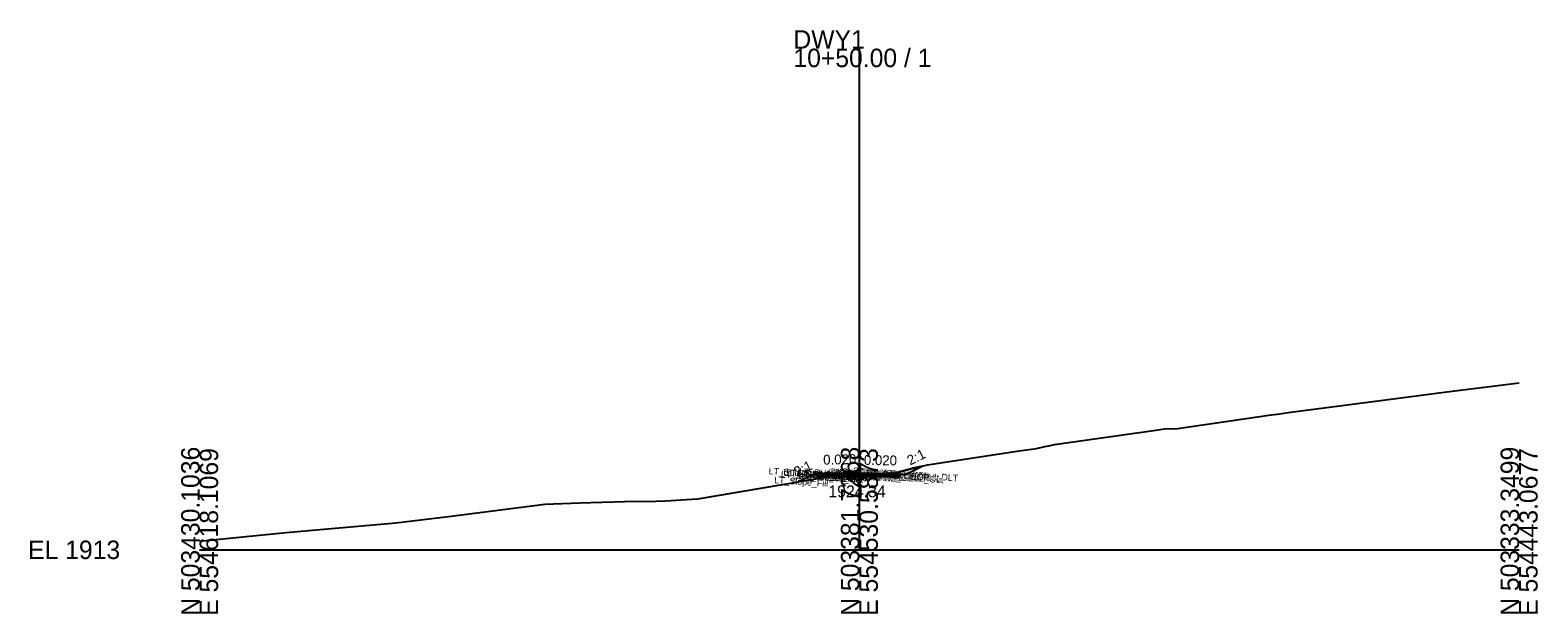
# Model space of a CAD drawing. Extents: x -26 to 203, y -10 to 1558.
# Drawn here: x -25.7 to 202.8, y 490.3 to 578.7 of the extents above; entities that cross this region are included whole.
import ezdxf

# ---------------------------------------------------------------- set-up
doc = ezdxf.new("R2010")
doc.units = 0
for name, color, linetype in [('Default', 7, 'Continuous'), ('Exist Cross Section Cell', 7, 'Continuous'), ('Exist XS Center Line Elevation Label', 7, 'Continuous'), ('Exist XS Ground Line', 7, 'Continuous'), ('Prop CMT Pvmt Course 1', 7, 'Continuous'), ('Prop CMT Pvmt Course 2', 7, 'Continuous'), ('Prop CMT Pvmt Surface', 7, 'Continuous'), ('Prop CMT Shld Paved Course 1', 7, 'Continuous'), ('Prop CMT Shld Paved Course 2', 7, 'Continuous'), ('Prop CMT Slope Grass', 7, 'Continuous'), ('Prop CMT Subgrade Earthwork', 7, 'Continuous'), ('Prop XS Earthwork Shape', 7, 'Continuous'), ('Prop XS SE Text', 7, 'Continuous'), ('Prop XS Side Slope Text', 7, 'Continuous'), ('Typical Text Asphalt at Bridge Approach CELL', 7, 'Continuous')]:
    doc.layers.add(name, color=color, linetype=linetype)

msp = doc.modelspace()

# ---------------------------------------------------------------- linework, layer by layer
at = {"layer": 'Exist Cross Section Cell'}
for p, q in [((100, 500), (100, 575.89)), ((0, 500), (100, 500)), ((100, 500), (200, 500))]:
    msp.add_line(p, q, dxfattribs=at)
at = {"layer": 'Exist XS Ground Line'}
for p, q in [((179, 522.6), (189.03, 523.93)), ((189.03, 523.93), (200, 525.3)), ((165.01, 520.8), (179, 522.6)), ((147.93, 518.32), (162.04, 520.41)), ((162.04, 520.41), (163.71, 520.6)), ((163.71, 520.6), (165.01, 520.8)), ((129.56, 515.96), (144.92, 518.1)), ((144.92, 518.1), (146.24, 518.34)), ((146.24, 518.34), (147.18, 518.35)), ((147.18, 518.35), (147.93, 518.32)), ((115.27, 513.63), (124.24, 515.01)), ((124.24, 515.01), (126.85, 515.36)), ((126.85, 515.36), (128.09, 515.66)), ((128.09, 515.66), (128.99, 515.8)), ((128.99, 515.8), (129.56, 515.96)), ((105.35, 511.63), (108.36, 512.4)), ((108.36, 512.4), (109.32, 512.63)), ((109.32, 512.63), (110.31, 512.87)), ((110.31, 512.87), (115.27, 513.63)), ((75.52, 507.74), (94.91, 511.02)), ((94.91, 511.02), (95.83, 511.17)), ((95.83, 511.17), (100, 511.34)), ((100, 511.34), (105, 511.54)), ((105, 511.54), (105.35, 511.63)), ((64.38, 507.31), (69.13, 507.38)), ((69.13, 507.38), (70.66, 507.4)), ((70.66, 507.4), (72.25, 507.52)), ((72.25, 507.52), (74.58, 507.66)), ((74.58, 507.66), (75.52, 507.74)), ((37.74, 505.03), (52.31, 506.92)), ((52.31, 506.92), (57.63, 507.12)), ((57.63, 507.12), (64.38, 507.31)), ((13.13, 502.6), (29.72, 504.11)), ((29.72, 504.11), (37.74, 505.03)), ((0, 501.33), (13.13, 502.6))]:
    msp.add_line(p, q, dxfattribs=at)
at = {"layer": 'Prop CMT Pvmt Course 1'}
for points in [[(100, 511.67), (95, 511.57)], [(95, 511.57), (95, 511.32)], [(95, 511.32), (100, 511.42)], [(100, 511.42), (100, 511.67)], [(100, 511.67), (105, 511.57)], [(100, 511.42), (100, 511.67)], [(105, 511.32), (100, 511.42)], [(105, 511.57), (105, 511.32)]]:
    msp.add_lwpolyline(points, dxfattribs=at)
msp.add_lwpolyline([(100, 511.42), (100, 511.54), (100, 511.54), (100, 511.42)], close=True, dxfattribs=at)
msp.add_lwpolyline([(100, 511.42), (100, 511.54), (100, 511.54), (100, 511.42)], close=True, dxfattribs=at)
at = {"layer": 'Prop CMT Pvmt Course 2'}
for points in [[(100, 511.42), (95, 511.32)], [(95, 511.32), (95, 511.07)], [(95, 511.07), (100, 511.17)], [(100, 511.17), (100, 511.42)], [(100, 511.17), (100, 511.42)], [(100, 511.42), (105, 511.32)], [(105, 511.07), (100, 511.17)], [(105, 511.32), (105, 511.07)]]:
    msp.add_lwpolyline(points, dxfattribs=at)
at = {"layer": 'Prop CMT Pvmt Surface'}
for points in [[(100, 511.67), (95, 511.57)], [(100, 511.67), (105, 511.57)]]:
    msp.add_lwpolyline(points, dxfattribs=at)
at = {"layer": 'Prop CMT Shld Paved Course 1'}
for points in [[(95, 511.57), (94.74, 511.31)], [(94.74, 511.31), (95, 511.32)], [(95, 511.32), (95, 511.57)], [(105, 511.57), (105.26, 511.31)], [(105, 511.32), (105, 511.57)], [(105.26, 511.31), (105, 511.32)]]:
    msp.add_lwpolyline(points, dxfattribs=at)
at = {"layer": 'Prop CMT Shld Paved Course 2'}
for points in [[(95, 511.32), (94.74, 511.31), (94.24, 511.3), (93.99, 511.05)], [(93.99, 511.05), (95, 511.07)], [(95, 511.07), (95, 511.32)], [(105, 511.32), (105.26, 511.31), (105.76, 511.3), (106.01, 511.05)], [(105, 511.07), (105, 511.32)], [(106.01, 511.05), (105, 511.07)]]:
    msp.add_lwpolyline(points, dxfattribs=at)
at = {"layer": 'Prop CMT Slope Grass'}
for points in [[(105, 511.57), (107, 511.41), (109.54, 512.68)], [(95, 511.57), (93, 511.41), (90.86, 510.34)]]:
    msp.add_lwpolyline(points, dxfattribs=at)
at = {"layer": 'Prop CMT Subgrade Earthwork'}
for points in [[(95, 511.07), (93.99, 511.05), (93.58, 511.45)], [(100, 511.17), (95, 511.07)], [(100, 511.17), (105, 511.07)], [(105, 511.07), (106.01, 511.05), (106.42, 511.45)]]:
    msp.add_lwpolyline(points, dxfattribs=at)
at = {"layer": 'Prop XS Earthwork Shape'}
for points in [[(106.42, 511.45), (107, 511.41), (109.54, 512.68), (109.32, 512.63), (108.36, 512.4), (105.35, 511.63), (105, 511.57)], [(95.23, 511.07), (95, 511.07), (93.99, 511.05), (93.58, 511.45), (93, 511.41), (90.86, 510.34), (94.91, 511.02)], [(95.23, 511.07), (95.83, 511.17), (100, 511.34), (105, 511.57), (106.42, 511.45), (106.01, 511.05), (105, 511.07), (100, 511.17)]]:
    msp.add_lwpolyline(points, close=True, dxfattribs=at)

# ---------------------------------------------------------------- texts
at = {"layer": 'Default'}
msp.add_text('-', height=0.0001, dxfattribs=at).set_placement((0, 500))
at = {"layer": 'Exist Cross Section Cell'}
for s, p in [('DWY1', (90, 575.89)), ('10+50.00 / 1', (90, 573.09)), ('EL 1913', (-26, 498.6))]:
    msp.add_text(s, height=2.8, dxfattribs=at).set_placement(p)
for s, p in [('N 503430.1036', (0, 490)), ('E 554618.1069', (2.8, 490)), ('N 503381.7268', (100, 490)), ('E 554530.5873', (102.8, 490)), ('N 503333.3499', (200, 490)), ('E 554443.0677', (202.8, 490))]:
    msp.add_text(s, height=2.8, rotation=90, dxfattribs=at).set_placement(p)
at = {"layer": 'Exist XS Center Line Elevation Label'}
msp.add_text('1924.34', height=1.8, dxfattribs=at).set_placement((95.29, 507.95))
at = {"layer": 'Prop XS SE Text'}
for rotation, p in [(1.1458, (94.53, 512.89)), (358.8542, (100.67, 512.87))]:
    msp.add_text('0.020', height=1.5, rotation=rotation, dxfattribs=at).set_placement(p)
at = {"layer": 'Prop XS Side Slope Text'}
for p in [(107.7, 512.76), (90.53, 511.01)]:
    msp.add_text('2:1', height=1.5, rotation=26.5651, dxfattribs=at).set_placement(p)
at = {"layer": 'Typical Text Asphalt at Bridge Approach CELL'}
for s, p in [('LT_Sub_Trench_Out_DLT', (86.22, 511.47)), ('LT_Sub_Trench_Out', (88.08, 510.96)), ('LT_GS_OS_CTL', (88.44, 511.23)), ('LT_PS2_Shelf_Out', (88.88, 511.18)), ('LT_PS2_OEOP', (90.51, 511.11)), ('LT_PV2_OEOT', (90.72, 511.12)), ('LT_PV1_OEOT', (90.84, 511.36)), ('RT_PV2_OEEOP', (95.31, 511.24)), ('RT_Sub_OEEOP', (95.33, 510.99)), ('LT_PV2_OEEOP', (95.37, 511.24)), ('LT_Sub_OEEOP', (95.39, 510.99)), ('RT_PV1_OEEOP', (95.43, 511.36)), ('LT_PV1_OEEOP', (95.49, 511.36)), ('RT_PV2_IEEOP', (95.69, 511.22)), ('LT_PV2_IEEOP', (95.75, 511.21)), ('RT_PV1_IEEOP', (95.81, 511.33)), ('LT_PV1_IEEOP', (95.87, 511.33)), ('PV2_PGL', (97.32, 511.1)), ('PV1_PGL', (97.44, 511.35)), ('RT_Sub_Trench_Out_DLT', (98.99, 511.47)), ('RT_Sub_Trench_Out', (100.04, 510.96)), ('RT_PS2_Shelf_Out', (100.33, 511.18)), ('RT_GS_OS_CTL', (100.46, 511.38)), ('RT_PV2_OEOT', (100.66, 511.12)), ('RT_PV1_OEOT', (100.78, 511.36)), ('RT_PS2_OEOP', (100.96, 511.11)), ('LT_Slope_Fill', (87.07, 510.1)), ('LT_Sub_OEOT', (90.74, 510.86)), ('RT_Sub_OEOT', (100.69, 510.87))]:
    msp.add_text(s, height=1, rotation=356, dxfattribs=at).set_placement(p)

doc.saveas('drawing.dxf')
